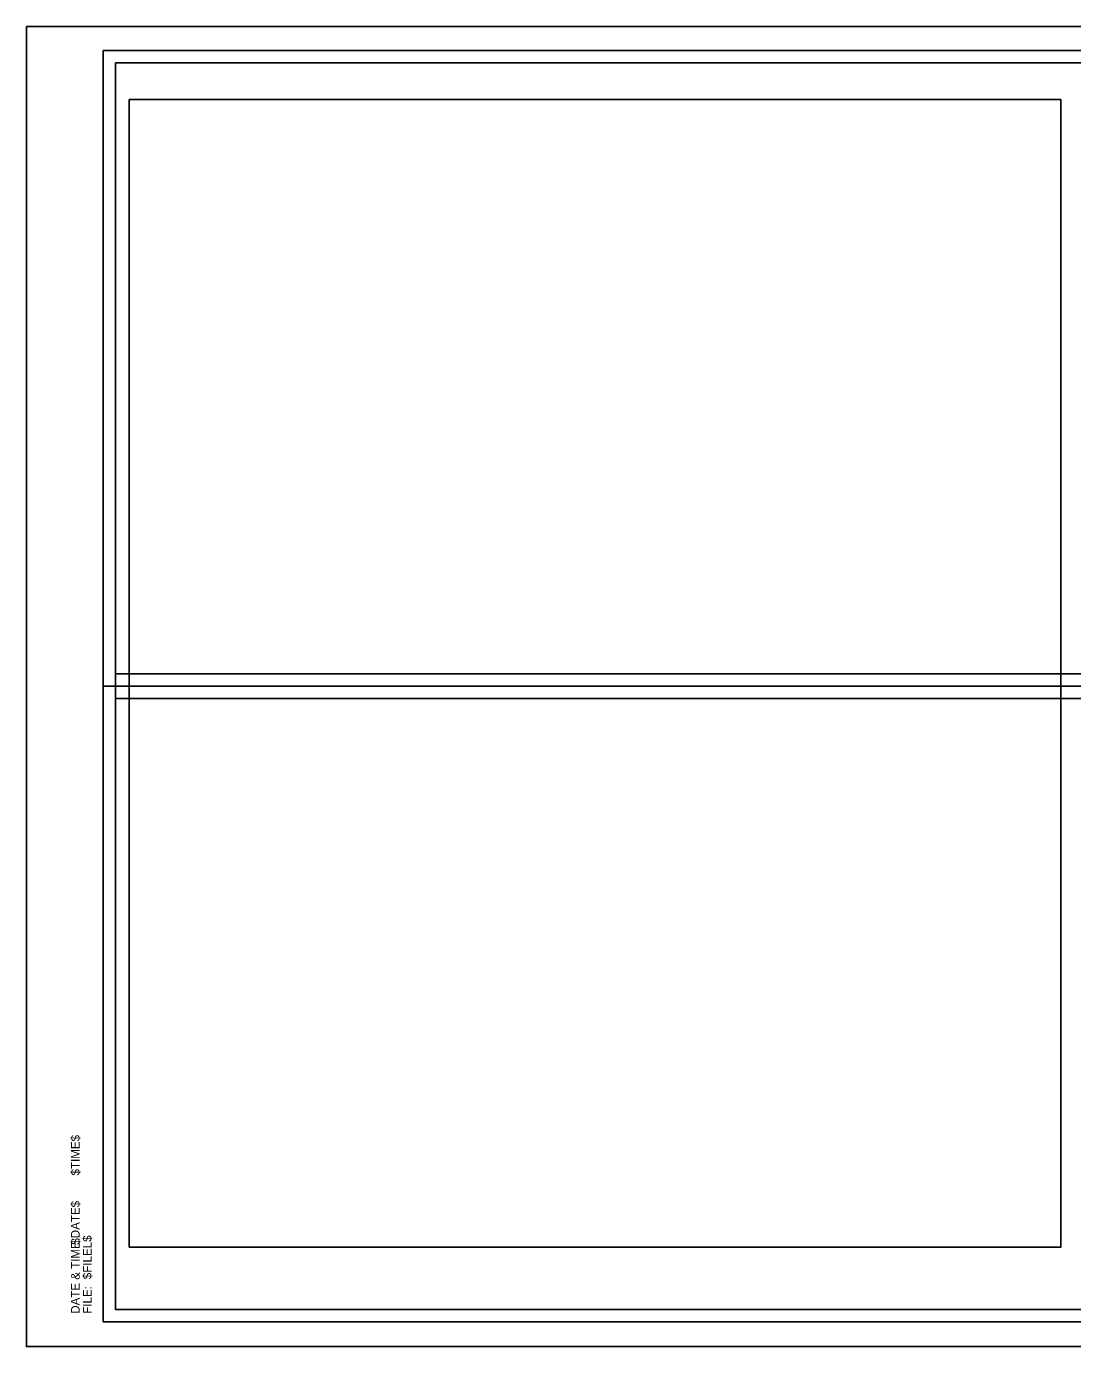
# Model space of a CAD drawing. Extents: x 1369290 to 1371547, y 379683 to 379897.
# Drawn here: x 1370386.1 to 1370555.2, y 379683.5 to 379896.8 of the extents above; entities that cross this region are included whole.
import ezdxf

# ---------------------------------------------------------------- set-up
doc = ezdxf.new("R2010")
doc.units = 0
for name, color, linetype in [('Default', 7, 'Continuous'), ('R_Border', 7, 'Continuous'), ('R_Border Notes', 7, 'Continuous'), ('R_Border Plan-Plan', 7, 'Continuous'), ('R_No Plot', 7, 'Continuous')]:
    doc.layers.add(name, color=color, linetype=linetype)

msp = doc.modelspace()

# ---------------------------------------------------------------- linework, layer by layer
at = {"layer": 'Default'}
msp.add_lwpolyline([(1370402.73, 379699.56), (1370553.3, 379699.56), (1370553.3, 379885), (1370402.73, 379885)], close=True, dxfattribs=at)
at = {"layer": 'R_Border'}
for p, q in [((1370398.53, 379892.93), (1370714.71, 379892.93)), ((1370398.53, 379687.47), (1370398.53, 379892.93)), ((1370551.05, 379892.67), (1370551.05, 379892.67)), ((1370551.05, 379892.67), (1370551.05, 379892.67)), ((1370398.53, 379687.47), (1370398.53, 379687.47)), ((1370714.71, 379687.47), (1370398.53, 379687.47))]:
    msp.add_line(p, q, dxfattribs=at)
at = {"layer": 'R_Border Plan-Plan'}
msp.add_line((1370398.53, 379790.2), (1370714.71, 379790.2), dxfattribs=at)
at = {"layer": 'R_No Plot'}
for points in [[(1370386.12, 379896.82), (1370719.46, 379896.82), (1370719.46, 379683.48), (1370386.12, 379683.48)], [(1370712.71, 379792.2), (1370400.53, 379792.2), (1370400.53, 379890.93), (1370650.07, 379890.93), (1370650.07, 379881.05), (1370667.61, 379881.05), (1370691.71, 379881.05), (1370691.71, 379858.71), (1370712.71, 379858.71)], [(1370400.53, 379890.93), (1370650.07, 379890.93), (1370650.07, 379881.05), (1370667.61, 379881.05), (1370691.71, 379881.05), (1370691.71, 379858.71), (1370712.71, 379858.71), (1370712.71, 379689.47), (1370400.53, 379689.47)], [(1370400.53, 379788.2), (1370712.71, 379788.2), (1370712.71, 379689.47), (1370400.53, 379689.47)]]:
    msp.add_lwpolyline(points, close=True, dxfattribs=at)

# ---------------------------------------------------------------- texts
at = {"layer": 'R_Border Notes'}
for s, height, p in [('$TIME$', 1.397, (1370394.73, 379711.14)), ('$DATE$', 1.397, (1370394.73, 379699.96)), ('DATE & TIME:', 1.3968, (1370394.73, 379688.79)), ('$FILEL$', 1.397, (1370396.65, 379694.38)), ('FILE: ', 1.397, (1370396.65, 379688.79))]:
    msp.add_text(s, height=height, rotation=90, dxfattribs=at).set_placement(p)

doc.saveas('drawing.dxf')
